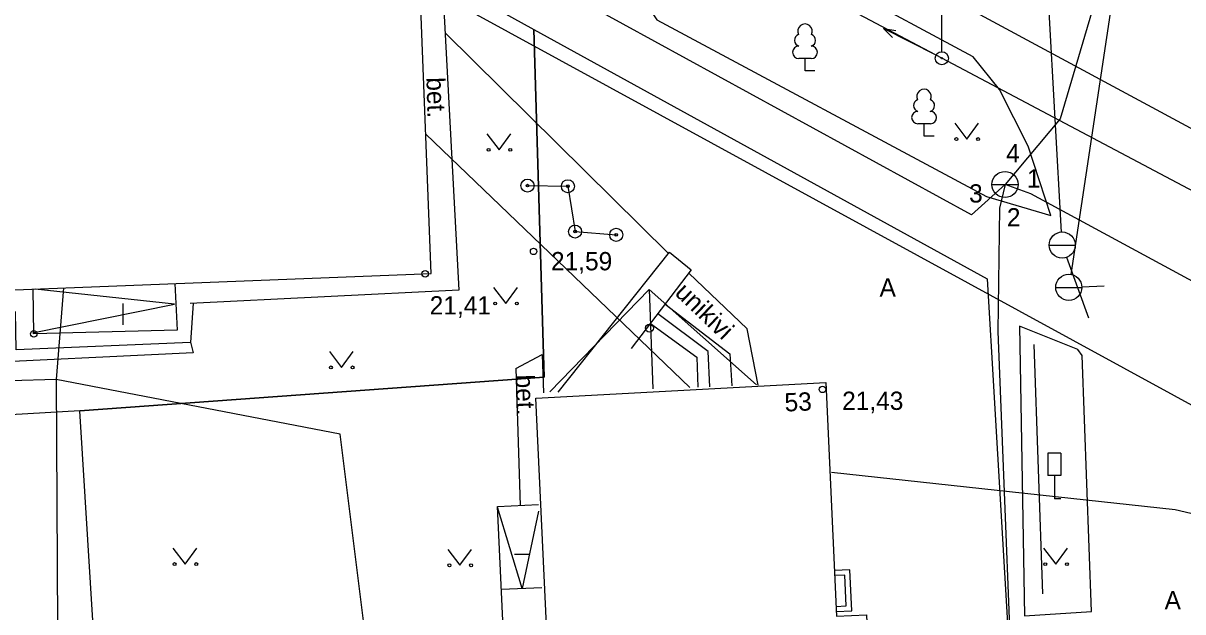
# Model space of a CAD drawing. Extents: x 714038 to 714279, y 6589845 to 6590041.
# Drawn here: x 714116.25 to 714160.6, y 6589933.15 to 6589955.67 of the extents above; entities that cross this region are included whole.
import ezdxf

# ---------------------------------------------------------------- set-up
doc = ezdxf.new("R2010")
doc.units = 0
for name, color, linetype in [('HALJASTUS', 7, 'Continuous'), ('HOONE', 7, 'Continuous'), ('HOONEDET', 7, 'Continuous'), ('KORGUS', 7, 'Continuous'), ('LIIKLUS', 7, 'Continuous'), ('MPKAABEL', 7, 'Continuous'), ('MPOHULIIN', 7, 'Continuous'), ('POST', 7, 'Continuous'), ('PUU', 7, 'Continuous'), ('SITRASS', 7, 'Continuous'), ('TEE', 7, 'Continuous'), ('TORU NR', 7, 'Continuous'), ('VKAEV', 7, 'Continuous'), ('VTRASS', 7, 'Continuous'), ('Слой 1', 7, 'Continuous')]:
    doc.layers.add(name, color=color, linetype=linetype)

msp = doc.modelspace()

# ---------------------------------------------------------------- linework, layer by layer
at = {"layer": 'HALJASTUS'}
for p, q in [((714133.985, 6589951.432), (714134.449, 6589950.826)), ((714134.449, 6589950.826), (714134.894, 6589951.432)), ((714151.875, 6589951.843), (714152.338, 6589951.236)), ((714152.338, 6589951.236), (714152.784, 6589951.843)), ((714134.238, 6589945.552), (714134.701, 6589944.946)), ((714134.701, 6589944.946), (714135.147, 6589945.552)), ((714127.957, 6589943.107), (714128.42, 6589942.5)), ((714128.42, 6589942.5), (714128.866, 6589943.107)), ((714121.977, 6589935.587), (714122.44, 6589934.98)), ((714122.44, 6589934.98), (714122.886, 6589935.587)), ((714132.487, 6589935.537), (714132.95, 6589934.93)), ((714132.95, 6589934.93), (714133.396, 6589935.537)), ((714155.276, 6589935.581), (714155.74, 6589934.974)), ((714155.74, 6589934.974), (714156.185, 6589935.581))]:
    msp.add_line(p, q, dxfattribs=at)
msp.add_lwpolyline([(714154.898, 6589943.375), (714155.236, 6589933.837)], dxfattribs=at)
for centre in [(714151.937, 6589951.236), (714152.766, 6589951.236), (714134.048, 6589950.826), (714134.877, 6589950.826), (714134.3, 6589944.946), (714135.129, 6589944.946), (714128.019, 6589942.5), (714128.848, 6589942.5), (714122.039, 6589934.98), (714122.868, 6589934.98), (714155.339, 6589934.974), (714156.168, 6589934.974), (714132.549, 6589934.93), (714133.378, 6589934.93)]:
    msp.add_circle(centre, 0.055, dxfattribs=at)
at = {"layer": 'HOONE'}
for points in [[(714037.81, 6590017.576), (714059.08, 6590006.51), (714072.38, 6589999.69), (714082.14, 6589994.37), (714104.85, 6589981.96), (714150.21, 6589957.43), (714183.55, 6589939.45), (714202.68, 6589928.99), (714214.04, 6589922.75), (714222.92, 6589918.06), (714237.47, 6589910.29), (714252.27, 6589902.23), (714256.602, 6589899.815), (714258.577, 6589898.715), (714261.69, 6589896.98)], [(714119.783, 6589956.463), (714090.49, 6589955.04), (714090.9, 6589944.49), (714131.853, 6589946.089), (714131.432, 6589956.918), (714122.304, 6589956.561), (714122.284, 6589957.061), (714119.765, 6589956.935), (714119.783, 6589956.463)], [(714136.395, 6589941.563), (714140.195, 6589945.484), (714144.294, 6589941.838)], [(714140.195, 6589945.484), (714140.334, 6589941.68)], [(714146.948, 6589941.92), (714147.35, 6589932.99), (714148.498, 6589933.042), (714148.695, 6589928.567), (714149.507, 6589928.603), (714150.093, 6589914.743), (714149.306, 6589914.708), (714149.578, 6589908.551), (714150.382, 6589908.586), (714151.015, 6589894.674), (714150.191, 6589894.637), (714150.455, 6589888.649), (714151.288, 6589888.686), (714151.897, 6589874.779), (714151.068, 6589874.742), (714151.263, 6589870.313), (714150.171, 6589870.264), (714150.579, 6589861.196), (714139.646, 6589860.738), (714135.859, 6589941.326), (714146.948, 6589941.92)], [(714147.342, 6589933.158), (714147.934, 6589933.185), (714147.863, 6589934.761), (714147.271, 6589934.735)]]:
    msp.add_lwpolyline(points, dxfattribs=at)
at = {"layer": 'HOONEDET'}
for p, q in [((714136.703, 6589941.548), (714140.967, 6589946.905)), ((714140.967, 6589946.905), (714141.795, 6589946.229)), ((714141.795, 6589946.229), (714139.498, 6589943.219)), ((714140.8, 6589944.924), (714143.279, 6589943.015)), ((714142.447, 6589943.114), (714140.514, 6589944.55)), ((714140.236, 6589944.185), (714142.013, 6589942.888)), ((714142.508, 6589941.76), (714142.447, 6589943.114)), ((714143.279, 6589943.015), (714143.352, 6589941.79)), ((714142.013, 6589942.888), (714142.048, 6589941.743)), ((714147.672, 6589934.553), (714147.28, 6589934.535)), ((714147.725, 6589933.375), (714147.672, 6589934.553)), ((714147.333, 6589933.358), (714147.725, 6589933.375))]:
    msp.add_line(p, q, dxfattribs=at)
for points in [[(714122.407, 6589957.455), (714130.601, 6589957.826), (714132.296, 6589956.921), (714132.905, 6589945.462), (714122.63, 6589944.95)], [(714122.05, 6589945.71), (714122.14, 6589943.92), (714116.65, 6589943.78), (714116.63, 6589945.49)], [(714116.61, 6589943.82), (714122.04, 6589944.92), (714116.71, 6589945.5)], [(714122.75, 6589944.96), (714122.65, 6589943.46), (714115.98, 6589943.17), (714115.95, 6589944.63), (714102.86, 6589944.21), (714102.85, 6589942.86)], [(714120.07, 6589944.13), (714120.07, 6589944.94)], [(714135.094, 6589942.456), (714135.26, 6589937.22)], [(714136.29, 6589929.62), (714134.74, 6589929.54), (714134.39, 6589937.18), (714135.95, 6589937.26)], [(714135.96, 6589937), (714135.33, 6589934.04), (714134.39, 6589937.15)], [(714135.04, 6589935.36), (714135.61, 6589935.36)], [(714136.09, 6589934.07), (714134.54, 6589934.01)]]:
    msp.add_lwpolyline(points, dxfattribs=at)
msp.add_circle((714140.199, 6589944.004), 0.15, dxfattribs=at)
at = {"layer": 'KORGUS'}
for centre in [(714135.77, 6589946.94), (714131.62, 6589946.08), (714116.65, 6589943.78), (714146.82, 6589941.66)]:
    msp.add_circle(centre, 0.125, dxfattribs=at)
at = {"layer": 'LIIKLUS'}
for p, q in [((714135.536, 6589949.455), (714137.08, 6589949.431)), ((714137.08, 6589949.431), (714137.354, 6589947.698)), ((714137.354, 6589947.698), (714138.93, 6589947.572))]:
    msp.add_line(p, q, dxfattribs=at)
for points in [[(714155.438, 6589939.218), (714155.438, 6589938.368)], [(714155.938, 6589939.218), (714155.438, 6589939.218)], [(714155.938, 6589939.218), (714155.938, 6589938.368)], [(714155.938, 6589938.368), (714155.438, 6589938.368)], [(714155.688, 6589938.368), (714155.688, 6589937.468)], [(714155.938, 6589937.468), (714155.688, 6589937.468)]]:
    msp.add_lwpolyline(points, dxfattribs=at)
for centre, radius in [((714135.536, 6589949.455), 0.25), ((714137.08, 6589949.431), 0.25), ((714135.536, 6589949.455), 0.05), ((714137.08, 6589949.431), 0.05), ((714137.354, 6589947.698), 0.25), ((714137.354, 6589947.698), 0.05), ((714138.93, 6589947.572), 0.25), ((714138.93, 6589947.572), 0.05)]:
    msp.add_circle(centre, radius, dxfattribs=at)
at = {"layer": 'MPKAABEL'}
for points in [[(714151.383, 6589954.327), (714124.725, 6589968.419)], [(714176.708, 6589940.841), (714176.463, 6589941.047), (714151.383, 6589954.327)], [(714117.51, 6589942.04), (714098.29, 6589941.48), (714082.52, 6589946.12), (714077.99, 6589948.22)], [(714117.79, 6589945.54), (714117.51, 6589942.04)], [(714117.51, 6589942.04), (714117.61, 6589923.16)], [(714137.96, 6589892.9), (714131.87, 6589892.68), (714130.99, 6589916.93), (714130.36, 6589924.03), (714128.37, 6589939.95), (714117.51, 6589942.04)]]:
    msp.add_lwpolyline(points, dxfattribs=at)
at = {"layer": 'MPOHULIIN'}
for p, q in [((714149.157, 6589955.464), (714149.49, 6589955.125)), ((714149.157, 6589955.464), (714149.627, 6589955.391)), ((714151.161, 6589954.441), (714149.157, 6589955.464))]:
    msp.add_line(p, q, dxfattribs=at)
at = {"layer": 'POST'}
msp.add_line((714151.383, 6589954.577), (714151.383, 6589956.577), dxfattribs=at)
for radius in [0.25, 0.0234]:
    msp.add_circle((714151.383, 6589954.327), radius, dxfattribs=at)
at = {"layer": 'PUU'}
for p, q in [((714146.39, 6589954.316), (714145.91, 6589954.316)), ((714146.15, 6589953.841), (714146.15, 6589954.316)), ((714146.53, 6589953.841), (714146.15, 6589953.841)), ((714150.943, 6589951.82), (714150.463, 6589951.82)), ((714150.703, 6589951.345), (714150.703, 6589951.82)), ((714151.083, 6589951.345), (714150.703, 6589951.345))]:
    msp.add_line(p, q, dxfattribs=at)
for centre, radius, start, end in [((714146.15, 6589955.361), 0.277, 332.5799, 207.4201), ((714145.98, 6589955.013), 0.233, 109.0217, 253.1415), ((714146.32, 6589955.013), 0.233, 286.8508, 70.9859), ((714145.912, 6589954.553), 0.238, 90.0016, 269.3953), ((714146.387, 6589954.553), 0.238, 270.6047, 89.9984), ((714150.703, 6589952.865), 0.277, 332.5799, 207.4201), ((714150.532, 6589952.518), 0.233, 109.0217, 253.1415), ((714150.873, 6589952.518), 0.233, 286.8508, 70.9859), ((714150.465, 6589952.058), 0.238, 90.0016, 269.3953), ((714150.94, 6589952.058), 0.238, 270.6047, 89.9984)]:
    msp.add_arc(centre, radius, start, end, dxfattribs=at)
at = {"layer": 'SITRASS'}
for points in [[(714173.493, 6589934.191), (714170.111, 6589936.05), (714128.857, 6589958.592)], [(714131.645, 6589951.429), (714141.742, 6589941.732)], [(714147.16, 6589938.495), (714160.301, 6589937.06), (714170.651, 6589934.64), (714173.442, 6589934.053)]]:
    msp.add_lwpolyline(points, dxfattribs=at)
at = {"layer": 'TEE'}
for points in [[(714139.925, 6589956.876), (714140.234, 6589956.163), (714140.484, 6589955.802), (714153.095, 6589949.039), (714155.555, 6589948.306), (714154.686, 6589950.968), (714153.587, 6589953.135), (714152.58, 6589954.383), (714147.598, 6589957.067), (714146.079, 6589957.558), (714142.852, 6589957.966), (714140.567, 6589958.688), (714136.498, 6589960.842), (714131.349, 6589963.609), (714129.959, 6589964.408), (714128.087, 6589965.9), (714126.521, 6589967.542), (714125.843, 6589968.233), (714123.973, 6589969.784), (714113.651, 6589975.327)], [(714132.382, 6589955.295), (714140.934, 6589946.862)], [(714144.356, 6589941.827), (714143.94, 6589943.979), (714141.704, 6589946.11)], [(714156.748, 6589942.959), (714156.578, 6589943.187), (714154.352, 6589944.081), (714154.543, 6589932.997)], [(714122.65, 6589943.47), (714122.75, 6589943.06), (714104.66, 6589942.19), (714094.76, 6589941.8), (714086.51, 6589941.37)], [(714135.094, 6589942.456), (714136.094, 6589942.992), (714136.148, 6589941.528)], [(714154.543, 6589932.997), (714157.11, 6589933.168), (714156.748, 6589942.959)]]:
    msp.add_lwpolyline(points, dxfattribs=at)
at = {"layer": 'VKAEV'}
for p, q in [((714153.298, 6589949.498), (714154.298, 6589949.498)), ((714155.487, 6589947.181), (714156.487, 6589947.181)), ((714155.738, 6589945.564), (714156.738, 6589945.564))]:
    msp.add_line(p, q, dxfattribs=at)
for centre in [(714153.798, 6589949.498), (714155.987, 6589947.181), (714156.238, 6589945.564)]:
    msp.add_circle(centre, 0.5, dxfattribs=at)
at = {"layer": 'VTRASS'}
for points in [[(714166.254, 6590040.965), (714165.506, 6590022.329), (714165.378, 6590008.723), (714165.284, 6589998.807), (714165.141, 6589983.322), (714160.198, 6589966.563), (714155.909, 6589952.01), (714153.798, 6589949.498)], [(714153.798, 6589949.498), (714152.517, 6589948.338), (714134.349, 6589958.294), (714134.144, 6589958.409), (714120.209, 6589965.86), (714104.085, 6589974.529), (714097.438, 6589978.146), (714096.95, 6589978.424), (714085.013, 6589984.641), (714084.705, 6589984.858), (714077.379, 6589988.763), (714061.877, 6589996.73), (714043.432, 6590006.628), (714037.81, 6590009.751)], [(714155.959, 6589947.68), (714154.745, 6589969.365)], [(714159.358, 6589966.391), (714159.218, 6589965.381), (714156.312, 6589946.059)], [(714153.798, 6589949.498), (714153.586, 6589948.597), (714153.525, 6589943.874), (714154.226, 6589926.095), (714154.986, 6589916.299), (714155.65, 6589900.618), (714157.564, 6589889.04), (714158.156, 6589881.355), (714159.479, 6589869.952), (714159.749, 6589859.617), (714159.92, 6589854.4), (714160.405, 6589845.18)], [(714219.771, 6589914.924), (714218.336, 6589915.691), (714204.329, 6589923.078), (714196.383, 6589927.305), (714185.655, 6589933.263), (714178.705, 6589937.104), (714170.033, 6589941.737), (714162.674, 6589944.874), (714154.781, 6589949.135), (714153.798, 6589949.498)], [(714156.999, 6589944.386), (714156.157, 6589946.71)], [(714156.738, 6589945.586), (714157.588, 6589945.624)]]:
    msp.add_lwpolyline(points, dxfattribs=at)
at = {"layer": 'Слой 1'}
for points in [[(714086, 6589982.93), (714135.78, 6589955.43), (714136.17, 6589942.13), (714118.41, 6589940.84), (714087.46, 6589939.06)], [(714153.12, 6589945.89), (714158.45, 6589855.54), (714156.4, 6589855.48), (714123.77, 6589854.49), (714118.41, 6589940.84), (714136.17, 6589942.13), (714135.78, 6589955.43)]]:
    msp.add_lwpolyline(points, close=True, dxfattribs=at)

# ---------------------------------------------------------------- texts
at = {"layer": 'HOONE'}
msp.add_text('53', height=0.7, rotation=2.582, dxfattribs=at).set_placement((714145.382, 6589940.811))
at = {"layer": 'HOONEDET'}
for p in [(714131.67, 6589953.59), (714135.079, 6589942.218)]:
    msp.add_text('bet.', height=0.7, rotation=271.6152, dxfattribs=at).set_placement(p)
at = {"layer": 'KORGUS'}
for s, p in [('21,59', (714136.434, 6589946.215)), ('21,41', (714131.795, 6589944.525)), ('21,43', (714147.569, 6589940.875))]:
    msp.add_text(s, height=0.7, dxfattribs=at).set_placement(p)
at = {"layer": 'TEE'}
msp.add_text('unikivi', height=0.7, rotation=316.217, dxfattribs=at).set_placement((714141.132, 6589945.311))
for p in [(714149, 6589945.209), (714159.902, 6589933.244)]:
    msp.add_text('A', height=0.7, dxfattribs=at).set_placement(p)
at = {"layer": 'TORU NR'}
for s, p in [('4', (714153.84, 6589950.341)), ('1', (714154.636, 6589949.375)), ('3', (714152.424, 6589948.807)), ('2', (714153.869, 6589947.893))]:
    msp.add_text(s, height=0.7, dxfattribs=at).set_placement(p)

doc.saveas('drawing.dxf')
